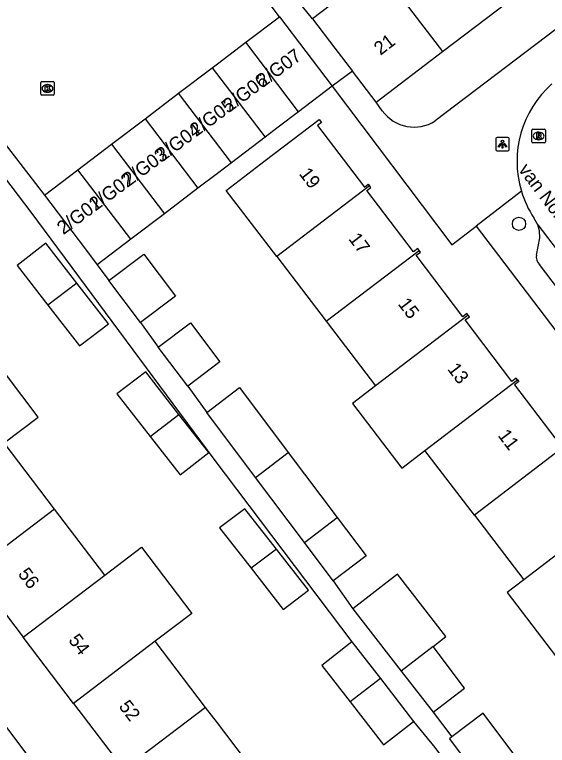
# Model space of a CAD drawing. Extents: x 160037 to 160839, y 385326 to 386441.
# Drawn here: x 160485 to 160524.3, y 385518 to 385571.9 of the extents above; entities that cross this region are included whole.
import ezdxf

# ---------------------------------------------------------------- set-up
doc = ezdxf.new("R2010")
doc.units = 0
for name, color, linetype in [('IMGEO_Boom', 7, 'Continuous'), ('IMGEO_Kolk', 7, 'Continuous'), ('IMGEO_Lichtpunt', 7, 'Continuous'), ('IMGEO_Openbare_ruimte_label', 7, 'Continuous'), ('IMGEO_Pand', 7, 'Continuous'), ('IMGEO_Pand_nummerreeks', 7, 'Continuous'), ('IMGEO_Rijbaan_lokaal_open', 7, 'Continuous'), ('IMGEO_Rioolput', 7, 'Continuous'), ('IMGEO_Voetpad_open', 7, 'Continuous')]:
    doc.layers.add(name, color=color, linetype=linetype)

msp = doc.modelspace()

# ---------------------------------------------------------------- linework, layer by layer
at = {"layer": 'IMGEO_Boom'}
msp.add_circle((160522.236, 385556.44), 0.489, dxfattribs=at)
at = {"layer": 'IMGEO_Kolk'}
for p, q in [((160486.964, 385566.009), (160486.964, 385566.861)), ((160487.039, 385566.935), (160487.891, 385566.935)), ((160487.452, 385566.715), (160487.477, 385566.715)), ((160487.965, 385566.861), (160487.965, 385566.009)), ((160487.891, 385565.935), (160487.039, 385565.935)), ((160487.475, 385566.155), (160487.45, 385566.155))]:
    msp.add_line(p, q, dxfattribs=at)
for points in [[(160486.964, 385566.009), (160486.964, 385566.861)], [(160487.039, 385566.935), (160487.891, 385566.935)], [(160487.965, 385566.861), (160487.965, 385566.009)], [(160487.285, 385566.635), (160487.408, 385566.635), (160487.408, 385566.484), (160487.538, 385566.635), (160487.702, 385566.635), (160487.556, 385566.484), (160487.709, 385566.235), (160487.557, 385566.235), (160487.472, 385566.399), (160487.408, 385566.332), (160487.408, 385566.235), (160487.285, 385566.235), (160487.285, 385566.635)], [(160487.891, 385565.935), (160487.039, 385565.935)]]:
    msp.add_lwpolyline(points, dxfattribs=at)
for centre, start, end in [((160487.041, 385566.859), 91.552, 178.448), ((160487.041, 385566.859), 91.552, 178.448), ((160487.889, 385566.859), 1.552, 88.448), ((160487.889, 385566.859), 1.552, 88.448), ((160487.041, 385566.011), 181.552, 268.448), ((160487.041, 385566.011), 181.552, 268.448), ((160487.889, 385566.011), 271.552, 358.448), ((160487.889, 385566.011), 271.552, 358.448)]:
    msp.add_arc(centre, 0.0765, start, end, dxfattribs=at)
for centre, major_axis, ratio, start_param, end_param in [((160487.451, 385566.435), (-0.387, 0.002), 0.722429, 4.712389, 7.853982), ((160487.476, 385566.435), (-0.39, 0.002), 0.717154, 1.570796, 4.712389)]:
    msp.add_ellipse(centre, major_axis=major_axis, ratio=ratio, start_param=start_param, end_param=end_param, dxfattribs=at)
at = {"layer": 'IMGEO_Lichtpunt'}
for p, q in [((160520.523, 385562.73), (160520.523, 385561.923)), ((160520.523, 385562.73), (160520.523, 385561.923)), ((160521.425, 385562.825), (160520.617, 385562.825)), ((160521.425, 385562.825), (160520.617, 385562.825)), ((160521.519, 385561.923), (160521.519, 385562.73)), ((160521.519, 385561.923), (160521.519, 385562.73)), ((160520.617, 385561.829), (160521.425, 385561.829)), ((160520.617, 385561.829), (160521.425, 385561.829))]:
    msp.add_line(p, q, dxfattribs=at)
for points in [[(160520.897, 385562.394), (160520.936, 385562.366), (160520.748, 385562.104), (160520.71, 385562.131), (160520.897, 385562.394)], [(160520.999, 385562.346), (160521.046, 385562.346), (160521.046, 385562.024), (160520.999, 385562.024), (160520.999, 385562.346)], [(160521.109, 385562.366), (160521.147, 385562.393), (160521.334, 385562.131), (160521.295, 385562.103), (160521.109, 385562.366)]]:
    msp.add_lwpolyline(points, dxfattribs=at)
msp.add_circle((160521.022, 385562.528), 0.0994, dxfattribs=at)
for centre, start, end in [((160520.617, 385562.73), 90, 180), ((160520.617, 385562.73), 90, 180), ((160521.425, 385562.73), 0, 90), ((160521.425, 385562.73), 0, 90), ((160520.617, 385561.923), 180, 270), ((160520.617, 385561.923), 180, 270), ((160521.425, 385561.923), 270, 0), ((160521.425, 385561.923), 270, 360)]:
    msp.add_arc(centre, 0.0946, start, end, dxfattribs=at)
at = {"layer": 'IMGEO_Pand'}
for points in [[(160511.909, 385575.297), (160507.017, 385571.576)], [(160511.909, 385575.297), (160516.589, 385569.15)], [(160516.589, 385569.15), (160521.452, 385572.849)], [(160502.091, 385569.839), (160504.567, 385571.72)], [(160504.567, 385571.72), (160508.463, 385566.591)], [(160507.017, 385571.576), (160508.667, 385569.406), (160509.95, 385567.72)], [(160499.614, 385567.958), (160500, 385568.251), (160502.091, 385569.839)], [(160505.987, 385564.71), (160502.091, 385569.839)], [(160511.694, 385565.427), (160516.589, 385569.15)], [(160497.138, 385566.077), (160499.614, 385567.958)], [(160499.614, 385567.958), (160503.511, 385562.829)], [(160511.694, 385565.427), (160509.95, 385567.72)], [(160508.463, 385566.591), (160505.987, 385564.71)], [(160494.662, 385564.196), (160497.138, 385566.077)], [(160501.034, 385560.948), (160497.138, 385566.077)], [(160505.987, 385564.71), (160504.482, 385563.567), (160503.511, 385562.829)], [(160492.186, 385562.314), (160494.662, 385564.196)], [(160494.662, 385564.196), (160498.558, 385559.067)], [(160504.377, 385554.02), (160500.643, 385558.909), (160503.522, 385561.108), (160507.495, 385564.143), (160507.667, 385563.917), (160507.383, 385563.7), (160510.832, 385559.156), (160511.116, 385559.372), (160511.213, 385559.245)], [(160503.511, 385562.829), (160501.034, 385560.948)], [(160489.709, 385560.433), (160492.186, 385562.314)], [(160492.186, 385562.314), (160496.082, 385557.185)], [(160501.034, 385560.948), (160500, 385560.162), (160498.558, 385559.067)], [(160487.233, 385558.552), (160489.709, 385560.433)], [(160493.605, 385555.304), (160489.709, 385560.433)], [(160511.213, 385559.245), (160504.377, 385554.02)], [(160514.866, 385554.485), (160514.769, 385554.612), (160514.46, 385554.376), (160511.026, 385558.9), (160511.31, 385559.118), (160511.213, 385559.245)], [(160498.558, 385559.067), (160496.082, 385557.185)], [(160487.233, 385558.552), (160490.257, 385554.571), (160491.129, 385553.423)], [(160496.082, 385557.185), (160493.605, 385555.304)], [(160489.631, 385552.062), (160487.332, 385555.017), (160485.217, 385553.371), (160487.498, 385550.438)], [(160493.605, 385555.304), (160491.129, 385553.423)], [(160508.018, 385549.254), (160514.866, 385554.485)], [(160518.488, 385549.7), (160518.395, 385549.821), (160518.093, 385549.59), (160514.654, 385554.121), (160514.963, 385554.358), (160514.866, 385554.485)], [(160491.983, 385552.267), (160494.561, 385554.205), (160496.896, 385551.099), (160494.318, 385549.161)], [(160504.377, 385554.02), (160508.018, 385549.254)], [(160494.318, 385549.161), (160491.983, 385552.267)], [(160489.631, 385552.062), (160487.498, 385550.438)], [(160487.498, 385550.438), (160489.827, 385547.444), (160491.96, 385549.068), (160489.631, 385552.062)], [(160518.488, 385549.7), (160511.661, 385544.485)], [(160522.123, 385544.928), (160522.026, 385545.055), (160521.715, 385544.818), (160518.273, 385549.353), (160518.576, 385549.585), (160518.488, 385549.7)], [(160495.637, 385547.341), (160498.003, 385549.134), (160500.18, 385546.263), (160497.813, 385544.469)], [(160508.018, 385549.254), (160511.661, 385544.485)], [(160497.813, 385544.469), (160495.637, 385547.341)], [(160484.264, 385540.271), (160486.776, 385542.184), (160483.062, 385547.06), (160482.861, 385546.907)], [(160497.16, 385542.385), (160494.714, 385545.53), (160492.58, 385543.906), (160495.027, 385540.761)], [(160515.303, 385539.717), (160522.123, 385544.928)], [(160522.123, 385544.928), (160522.22, 385544.801), (160521.909, 385544.563), (160525.343, 385540.038), (160525.666, 385540.285), (160525.763, 385540.158)], [(160499.214, 385542.524), (160501.625, 385544.367), (160505.226, 385539.57)], [(160511.661, 385544.485), (160509.957, 385543.183), (160513.599, 385538.414), (160515.303, 385539.717)], [(160502.814, 385537.727), (160499.214, 385542.524)], [(160495.027, 385540.761), (160497.16, 385542.385)], [(160495.027, 385540.761), (160497.242, 385537.915), (160499.357, 385539.561), (160497.16, 385542.385)], [(160487.978, 385535.394), (160484.264, 385540.271)], [(160525.763, 385540.158), (160518.946, 385534.949)], [(160502.814, 385537.727), (160505.226, 385539.57)], [(160505.226, 385539.57), (160508.829, 385534.77)], [(160518.946, 385534.949), (160515.303, 385539.717)], [(160506.417, 385532.927), (160502.814, 385537.727)], [(160487.978, 385535.394), (160481.957, 385530.81)], [(160491.692, 385530.517), (160487.978, 385535.394)], [(160504.347, 385532.445), (160502.03, 385535.422), (160500.161, 385533.999), (160502.479, 385531.023)], [(160518.946, 385534.949), (160522.589, 385530.179)], [(160529.37, 385535.362), (160522.589, 385530.179)], [(160506.417, 385532.927), (160508.829, 385534.77)], [(160508.829, 385534.77), (160510.959, 385531.932), (160508.532, 385530.11)], [(160508.532, 385530.11), (160506.417, 385532.927)], [(160491.692, 385530.517), (160494.396, 385532.576), (160498.11, 385527.697), (160495.407, 385525.64)], [(160504.347, 385532.445), (160502.479, 385531.023)], [(160502.479, 385531.023), (160504.851, 385527.975), (160506.704, 385529.418), (160504.347, 385532.445)], [(160481.957, 385530.81), (160485.671, 385525.934)], [(160515.909, 385525.256), (160516.849, 385525.986), (160513.267, 385530.596), (160509.975, 385528.038)], [(160485.671, 385525.934), (160491.692, 385530.517)], [(160522.589, 385530.179), (160521.355, 385529.236), (160524.997, 385524.469), (160526.231, 385525.412)], [(160509.975, 385528.038), (160513.557, 385523.428)], [(160489.386, 385521.057), (160485.671, 385525.934)], [(160495.407, 385525.64), (160489.386, 385521.057)], [(160499.121, 385520.763), (160495.407, 385525.64)], [(160509.919, 385525.592), (160507.689, 385523.863), (160509.776, 385521.172)], [(160509.919, 385525.592), (160512.021, 385522.881)], [(160515.909, 385525.256), (160513.557, 385523.428)], [(160515.909, 385520.4), (160518.224, 385522.168), (160515.909, 385525.256)], [(160513.557, 385523.428), (160515.909, 385520.4)], [(160512.021, 385522.881), (160509.776, 385521.172)], [(160512.021, 385522.881), (160514.466, 385519.728)], [(160489.386, 385521.057), (160493.1, 385516.18)], [(160509.776, 385521.172), (160512.237, 385517.999), (160514.466, 385519.728)], [(160499.121, 385520.763), (160493.1, 385516.18)], [(160502.832, 385515.885), (160500, 385519.609), (160499.121, 385520.763)], [(160523.194, 385515.539), (160519.594, 385520.34), (160517.295, 385518.584)], [(160517.295, 385518.584), (160517.11, 385518.443), (160520.71, 385513.641)]]:
    msp.add_lwpolyline(points, dxfattribs=at)
at = {"layer": 'IMGEO_Rijbaan_lokaal_open'}
for points in [[(160466.255, 385586.22), (160472.748, 385577.368), (160487.233, 385558.552)], [(160504.567, 385571.72), (160496.589, 385582.29)], [(160523.637, 385556.372), (160523.335, 385556.877)], [(160523.637, 385556.372), (160548.896, 385523.27)]]:
    msp.add_lwpolyline(points, dxfattribs=at)
for centre, radius, start, end in [((160529.705, 385561.051), 7.615, 131.409, 196.7806), ((160529.652, 385561.025), 7.557, 196.7115, 213.2905)]:
    msp.add_arc(centre, radius, start, end, dxfattribs=at)
at = {"layer": 'IMGEO_Rioolput'}
for p, q in [((160523.187, 385562.498), (160523.187, 385563.35)), ((160523.262, 385563.424), (160524.114, 385563.424)), ((160523.675, 385563.204), (160523.7, 385563.204)), ((160524.188, 385563.35), (160524.188, 385562.498)), ((160524.114, 385562.424), (160523.262, 385562.424)), ((160523.698, 385562.644), (160523.673, 385562.644))]:
    msp.add_line(p, q, dxfattribs=at)
for points in [[(160523.187, 385562.498), (160523.187, 385563.35)], [(160523.262, 385563.424), (160524.114, 385563.424)], [(160523.776, 385563.122), (160523.524, 385563.124), (160523.524, 385562.724)], [(160523.702, 385563.043), (160523.648, 385563.043), (160523.648, 385562.962)], [(160523.648, 385562.962), (160523.7, 385562.962)], [(160524.188, 385563.35), (160524.188, 385562.498)], [(160524.114, 385562.424), (160523.262, 385562.424)], [(160523.524, 385562.724), (160523.648, 385562.724), (160523.648, 385562.886), (160523.659, 385562.886)], [(160523.706, 385562.857), (160523.777, 385562.724), (160523.917, 385562.724), (160523.852, 385562.85)]]:
    msp.add_lwpolyline(points, dxfattribs=at)
for centre, radius, start, end in [((160523.264, 385563.348), 0.0765, 91.552, 178.448), ((160523.264, 385563.348), 0.0765, 91.552, 178.448), ((160523.684, 385563.151), 0.19, 274.7715, 282.9687), ((160523.708, 385562.947), 0.0964, 77.0061, 93.1865), ((160523.722, 385563.004), 0.0378, 276.6634, 79.6772), ((160523.775, 385563.012), 0.109, 350.3612, 89.416), ((160523.773, 385563.012), 0.112, 277.5842, 350.9817), ((160524.112, 385563.348), 0.0765, 1.552, 88.448), ((160524.112, 385563.348), 0.0765, 1.552, 88.448), ((160523.264, 385562.5), 0.0765, 181.552, 268.448), ((160523.264, 385562.5), 0.0765, 181.552, 268.448), ((160523.658, 385562.833), 0.0533, 26.0293, 88.6989), ((160523.757, 385562.797), 0.108, 29.5134, 73.7905), ((160524.112, 385562.5), 0.0765, 271.552, 358.448), ((160524.112, 385562.5), 0.0765, 271.552, 358.448)]:
    msp.add_arc(centre, radius, start, end, dxfattribs=at)
for centre, major_axis, ratio, start_param, end_param in [((160523.674, 385562.924), (-0.387, 0.002), 0.722429, 4.712389, 7.853982), ((160523.699, 385562.924), (-0.39, 0.002), 0.717154, 1.570796, 4.712389)]:
    msp.add_ellipse(centre, major_axis=major_axis, ratio=ratio, start_param=start_param, end_param=end_param, dxfattribs=at)
at = {"layer": 'IMGEO_Voetpad_open'}
for points in [[(160569.788, 385604.966), (160548.164, 385588.386), (160542.084, 385583.823), (160516.064, 385564.038)], [(160464.999, 385585.276), (160486.228, 385557.31), (160499.726, 385539.086), (160509.919, 385525.592)], [(160507.017, 385571.576), (160500.441, 385579.678)], [(160507.161, 385489.347), (160500, 385498.52), (160498.893, 385500), (160484.853, 385518.765), (160461.114, 385550.049), (160445.996, 385569.716)], [(160509.95, 385567.72), (160508.463, 385566.591)], [(160508.463, 385566.591), (160517.273, 385554.899), (160519.066, 385556.27)], [(160512.156, 385564.786), (160511.694, 385565.427)], [(160522.414, 385558.852), (160519.066, 385556.27)], [(160519.066, 385556.27), (160546.817, 385519.818)], [(160523.537, 385554.14), (160523.765, 385555.418), (160523.74, 385555.914), (160523.637, 385556.372)], [(160491.129, 385553.423), (160491.983, 385552.267)], [(160545.755, 385524.475), (160523.741, 385553.434)], [(160494.318, 385549.161), (160495.637, 385547.341)], [(160497.813, 385544.469), (160499.214, 385542.524)], [(160508.532, 385530.11), (160509.975, 385528.038)], [(160515.909, 385520.4), (160517.295, 385518.584)], [(160514.466, 385519.728), (160516.042, 385517.796), (160517.221, 385516.201)]]:
    msp.add_lwpolyline(points, dxfattribs=at)
for centre, radius, start, end in [((160514.505, 385566.477), 2.894, 215.743, 302.586), ((160524.24, 385553.961), 0.725, 165.6679, 226.5656)]:
    msp.add_arc(centre, radius, start, end, dxfattribs=at)

# ---------------------------------------------------------------- texts
at = {"layer": 'IMGEO_Openbare_ruimte_label'}
msp.add_text('van Norenburchstraat', height=1, rotation=306.9959, dxfattribs=at).set_placement((160522.155, 385560.43))
at = {"layer": 'IMGEO_Pand_nummerreeks'}
for s, rotation, p in [('21', 37.2583, (160512.018, 385568.838)), ('2/G07', 36.442, (160503.357, 385566.473)), ('2/G06', 36.442, (160500.889, 385564.65)), ('2/G05', 36.442, (160498.42, 385562.827)), ('2/G04', 36.442, (160495.951, 385561.004)), ('2/G03', 36.442, (160493.482, 385559.181)), ('19', 307.2019, (160505.977, 385560.126)), ('2/G02', 36.442, (160491.008, 385557.355)), ('2/G01', 36.442, (160488.633, 385555.601)), ('17', 307.2019, (160509.623, 385555.322)), ('15', 307.2019, (160513.269, 385550.519)), ('13', 307.2019, (160516.915, 385545.716)), ('11', 307.2019, (160520.63, 385540.822)), ('56', 307.2573, (160485.247, 385530.595)), ('54', 307.2592, (160488.966, 385525.708)), ('52', 307.2573, (160492.681, 385520.822))]:
    msp.add_text(s, height=1, rotation=rotation, dxfattribs=at).set_placement(p)

doc.saveas('drawing.dxf')
